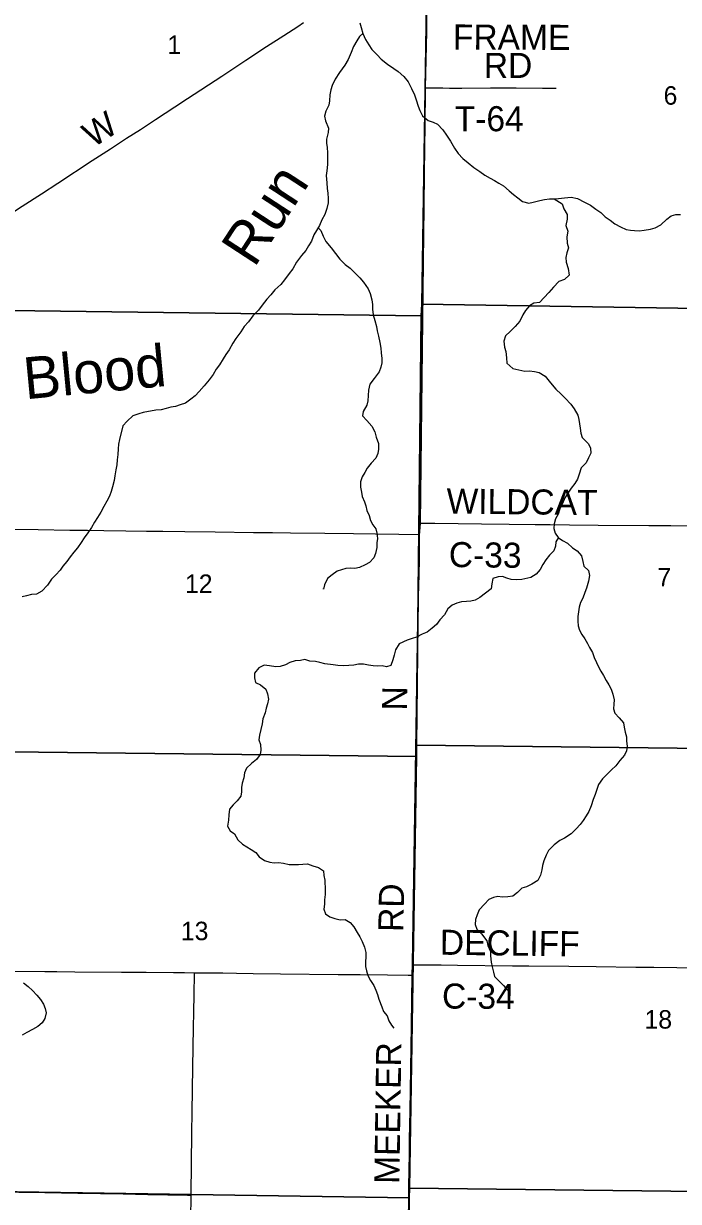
# Model space of a CAD drawing. Extents: x 1584893 to 1934202, y 663575 to 1091909.
# Drawn here: x 1740237 to 1748072, y 948034 to 962130 of the extents above; entities that cross this region are included whole.
import ezdxf

# ---------------------------------------------------------------- set-up
doc = ezdxf.new("R2010")
doc.units = 0
for name, color, linetype in [('GM_X_County_Road', 7, 'Continuous'), ('GM_X_County_Road_Text', 7, 'Continuous'), ('GM_X_Minor_River', 7, 'Continuous'), ('GM_X_Minor_River_Text', 7, 'Continuous'), ('GM_X_Section', 7, 'Continuous'), ('GM_X_Section_Text', 7, 'Continuous'), ('GM_X_Township', 7, 'Continuous'), ('GM_X_Township_Road', 7, 'Continuous'), ('GM_X_Township_Road_Text', 7, 'Continuous')]:
    doc.layers.add(name, color=color, linetype=linetype)

msp = doc.modelspace()

# ---------------------------------------------------------------- linework, layer by layer
at = {"layer": 'GM_X_County_Road'}
for points in [[(1745047, 961359), (1745060, 962035), (1745060, 962094), (1745063, 962269), (1745065, 962378), (1745071, 962804), (1745072, 962833), (1745078, 963198), (1745078, 963259)], [(1744979, 956151), (1744979, 956193), (1744982, 956456), (1744985, 956653), (1744988, 956866), (1744990, 957030), (1744996, 957243), (1744999, 957637), (1745000, 957785), (1745002, 957916), (1745002, 958014), (1745008, 958293), (1745013, 958621), (1745015, 958867), (1745022, 959278), (1745030, 959934), (1745034, 960361), (1745038, 960639), (1745040, 960918), (1745046, 961329), (1745047, 961359)], [(1744976, 956013), (1744977, 956073), (1744979, 956151)], [(1744979, 956151), (1745004, 956151), (1745159, 956149), (1745717, 956141), (1746045, 956139), (1746357, 956136), (1746537, 956134), (1746767, 956132), (1747111, 956128), (1747718, 956124), (1747980, 956121), (1748620, 956114), (1749014, 956110), (1749342, 956108), (1749899, 956101), (1750293, 956098), (1750752, 956093), (1751097, 956091), (1751474, 956089), (1751818, 956090), (1752179, 956091), (1752183, 956091)], [(1739718, 956080), (1739755, 956080), (1740411, 956074), (1740789, 956068), (1741002, 956065), (1741199, 956062), (1741461, 956059), (1741707, 956057), (1741904, 956056), (1742167, 956052), (1742528, 956047), (1742987, 956040), (1743217, 956039), (1743430, 956036), (1743841, 956032), (1744185, 956027), (1744448, 956023), (1744727, 956018), (1744957, 956014), (1744976, 956013)], [(1744892, 950867), (1744895, 951074), (1744900, 951378), (1744905, 951681), (1744909, 951993), (1744920, 952633), (1744925, 953027), (1744930, 953289), (1744934, 953486), (1744939, 953864), (1744941, 954060), (1744944, 954307), (1744947, 954421), (1744954, 954749), (1744957, 954897), (1744960, 955028), (1744962, 955143), (1744963, 955274), (1744969, 955537), (1744973, 955717), (1744975, 955963), (1744976, 956013)], [(1739680, 950791), (1739882, 950789), (1740129, 950788), (1740490, 950787), (1740637, 950785), (1740850, 950783), (1741408, 950779), (1741704, 950777), (1742032, 950773), (1742163, 950772), (1742283, 950771)], [(1744890, 950741), (1744891, 950812), (1744892, 950867)], [(1744892, 950867), (1744922, 950867), (1745070, 950867), (1745233, 950864), (1745430, 950861), (1746086, 950854), (1746283, 950852), (1746759, 950848), (1747087, 950844), (1747562, 950839), (1747776, 950838), (1748054, 950834), (1748399, 950829)], [(1742242, 948109), (1742242, 948116), (1742252, 948854), (1742256, 949100), (1742263, 949641), (1742272, 950117), (1742275, 950297), (1742277, 950511), (1742282, 950756), (1742283, 950771)], [(1742283, 950771), (1742442, 950769), (1742622, 950768), (1742786, 950766), (1742983, 950763), (1743312, 950759), (1744001, 950751), (1744263, 950749), (1744591, 950745), (1744837, 950742), (1744890, 950741)], [(1744824, 945592), (1744824, 945594), (1744825, 945791), (1744828, 946070), (1744832, 946513), (1744835, 946776), (1744835, 946989), (1744838, 947301), (1744841, 947695), (1744846, 948187), (1744850, 948433), (1744854, 948581), (1744856, 948777), (1744859, 948941), (1744861, 949122), (1744870, 949614), (1744874, 949893), (1744877, 950123), (1744884, 950435), (1744889, 950681), (1744890, 950741)], [(1739630, 948155), (1739854, 948154), (1740181, 948146), (1740329, 948144), (1740493, 948141), (1740887, 948133), (1741428, 948123), (1741723, 948118), (1742198, 948109), (1742242, 948109)], [(1742175, 944169), (1742176, 944279), (1742187, 944853), (1742189, 945050), (1742192, 945230), (1742198, 945525), (1742204, 945902), (1742216, 946542), (1742221, 946837), (1742227, 947181), (1742238, 947821), (1742242, 948109)]]:
    msp.add_lwpolyline(points, dxfattribs=at)
at = {"layer": 'GM_X_Minor_River'}
for points in [[(1744259, 962137), (1744275, 962084), (1744298, 962012), (1744327, 961939), (1744367, 961877), (1744404, 961820), (1744466, 961757), (1744517, 961702), (1744593, 961643), (1744667, 961592), (1744718, 961556), (1744786, 961495), (1744837, 961432), (1744879, 961351), (1744916, 961275), (1744934, 961218), (1744959, 961142), (1744978, 961089), (1745010, 961025), (1745077, 960970), (1745137, 960949), (1745191, 960925), (1745255, 960858), (1745298, 960793), (1745344, 960722), (1745393, 960640), (1745436, 960573), (1745494, 960516), (1745556, 960463), (1745623, 960406), (1745697, 960358), (1745757, 960317), (1745819, 960280), (1745870, 960253), (1745924, 960221), (1745978, 960186), (1746046, 960129), (1746097, 960086), (1746151, 960044), (1746207, 960001), (1746281, 959982), (1746335, 959994), (1746414, 960013), (1746468, 960025), (1746528, 960032), (1746584, 960033)], [(1744298, 962011), (1744255, 961976), (1744225, 961922), (1744186, 961856), (1744157, 961782), (1744120, 961700), (1744079, 961630), (1744018, 961543), (1743965, 961465), (1743928, 961389), (1743912, 961335), (1743903, 961275), (1743898, 961205), (1743890, 961153), (1743853, 961081), (1743836, 961023), (1743850, 960964), (1743885, 960878), (1743882, 960825), (1743863, 960747), (1743863, 960697), (1743868, 960647), (1743874, 960581), (1743875, 960502), (1743874, 960444), (1743865, 960368), (1743859, 960310), (1743866, 960223), (1743871, 960157), (1743877, 960101), (1743880, 960036), (1743880, 959986), (1743867, 959916), (1743840, 959844), (1743807, 959782), (1743776, 959712), (1743740, 959652), (1743711, 959600), (1743684, 959526), (1743648, 959471), (1743613, 959415), (1743562, 959355), (1743503, 959273), (1743458, 959193), (1743413, 959140), (1743358, 959062), (1743316, 959006), (1743245, 958943), (1743196, 958883), (1743149, 958831), (1743090, 958761), (1743048, 958700), (1742981, 958630), (1742930, 958562), (1742877, 958503), (1742836, 958439), (1742775, 958359), (1742741, 958303), (1742698, 958227), (1742659, 958169), (1742624, 958116), (1742583, 958046), (1742543, 957994), (1742504, 957928), (1742457, 957868), (1742398, 957793), (1742337, 957727), (1742291, 957673), (1742240, 957634), (1742173, 957588), (1742109, 957567), (1742055, 957547), (1741998, 957538), (1741944, 957524), (1741884, 957509), (1741820, 957505), (1741669, 957477), (1741616, 957461), (1741544, 957434), (1741475, 957370), (1741426, 957316), (1741384, 957153)], [(1746584, 960033), (1746682, 959974), (1746701, 959912), (1746739, 959845), (1746740, 959787), (1746723, 959715), (1746749, 959646), (1746736, 959576), (1746741, 959502), (1746755, 959447), (1746738, 959385), (1746723, 959329), (1746727, 959273), (1746752, 959199), (1746763, 959120), (1746709, 959066), (1746642, 959043), (1746579, 958977), (1746520, 958910), (1746466, 958850), (1746411, 958792), (1746343, 958783), (1746290, 958751), (1746243, 958694), (1746211, 958642), (1746176, 958570), (1746117, 958504), (1746058, 958445), (1746002, 958391), (1745985, 958327), (1745990, 958257), (1746008, 958204), (1746017, 958130), (1746018, 958064), (1746090, 958001), (1746164, 957984), (1746236, 957971), (1746290, 957973), (1746350, 957966), (1746404, 957955), (1746476, 957908), (1746541, 957831), (1746605, 957755), (1746668, 957696), (1746718, 957645), (1746783, 957574), (1746823, 957521), (1746868, 957445), (1746882, 957390), (1746889, 957340), (1746897, 957286), (1746906, 957227), (1746922, 957175)], [(1746584, 960033), (1746638, 960035), (1746707, 960046), (1746787, 960051), (1746863, 960035), (1746949, 959994), (1747021, 959955), (1747085, 959908), (1747144, 959867), (1747196, 959818), (1747254, 959776), (1747313, 959733), (1747377, 959698), (1747445, 959667), (1747497, 959659), (1747547, 959652), (1747601, 959650), (1747664, 959657), (1747738, 959670), (1747792, 959686), (1747863, 959721), (1747934, 959787), (1747986, 959828), (1748041, 959846), (1748095, 959845)], [(1743760, 959685), (1743794, 959654), (1743821, 959587), (1743855, 959521), (1743918, 959444), (1744021, 959312), (1744083, 959247), (1744144, 959201), (1744200, 959146), (1744259, 959087), (1744305, 959036), (1744360, 958956), (1744382, 958901), (1744403, 958825), (1744411, 958768), (1744412, 958710), (1744421, 958642), (1744439, 958577), (1744460, 958505), (1744469, 958451), (1744483, 958388), (1744498, 958314), (1744511, 958245), (1744517, 958189), (1744524, 958123), (1744522, 958069), (1744511, 958018), (1744492, 957960), (1744431, 957883), (1744381, 957813), (1744364, 957743), (1744359, 957677), (1744356, 957614), (1744346, 957564), (1744301, 957487), (1744292, 957434), (1744346, 957378), (1744405, 957311), (1744441, 957244), (1744456, 957180)], [(1741384, 957153), (1741375, 957095), (1741370, 957041), (1741365, 956971), (1741357, 956907), (1741353, 956849), (1741342, 956789), (1741328, 956719), (1741321, 956663), (1741302, 956587), (1741285, 956531), (1741264, 956473), (1741235, 956416), (1741196, 956352), (1741161, 956283), (1741122, 956219), (1741087, 956161), (1741050, 956100), (1741007, 956036), (1740964, 955977), (1740925, 955918), (1740882, 955856), (1740839, 955803), (1740794, 955749), (1740755, 955692), (1740706, 955638), (1740677, 955587), (1740624, 955534), (1740573, 955480), (1740522, 955409), (1740456, 955336), (1740392, 955303), (1740334, 955296), (1740271, 955281), (1740221, 955270)], [(1744456, 957180), (1744483, 957103), (1744482, 957038), (1744475, 956986), (1744452, 956929), (1744397, 956867), (1744350, 956810), (1744321, 956758), (1744290, 956705), (1744267, 956647), (1744268, 956581), (1744279, 956521), (1744290, 956470), (1744317, 956408), (1744334, 956357), (1744345, 956301), (1744374, 956242), (1744387, 956184), (1744417, 956131), (1744450, 956081), (1744465, 956030), (1744470, 955966), (1744463, 955914), (1744464, 955858), (1744449, 955788), (1744426, 955736), (1744375, 955679), (1744323, 955652), (1744258, 955621), (1744202, 955610), (1744146, 955611), (1744094, 955608), (1744043, 955594), (1743989, 955577), (1743930, 955534), (1743875, 955487), (1743836, 955413), (1743825, 955361), (1743825, 955367)], [(1746922, 957175), (1746998, 957100), (1747019, 957049), (1747024, 956987), (1746997, 956931), (1746970, 956872), (1746909, 956812), (1746886, 956739), (1746865, 956677), (1746832, 956625), (1746789, 956568), (1746750, 956508), (1746711, 956453), (1746686, 956385), (1746655, 956321), (1746634, 956260), (1746601, 956202), (1746584, 956142), (1746583, 956086), (1746596, 956032), (1746633, 955981), (1746684, 955944), (1746744, 955913), (1746805, 955854), (1746861, 955821), (1746914, 955760), (1746929, 955692), (1746940, 955635), (1746997, 955584), (1747010, 955524), (1746997, 955456), (1746973, 955374), (1746952, 955320), (1746927, 955255), (1746902, 955201), (1746883, 955147), (1746877, 955089), (1746870, 955033), (1746869, 954979), (1746874, 954921), (1746887, 954870), (1746918, 954820), (1746951, 954765), (1746984, 954712), (1747008, 954662), (1747043, 954603), (1747062, 954543), (1747091, 954482), (1747116, 954432), (1747143, 954381), (1747176, 954328), (1747207, 954268), (1747239, 954215), (1747268, 954165), (1747287, 954104), (1747304, 954036), (1747299, 953986), (1747294, 953930), (1747311, 953875), (1747362, 953822), (1747413, 953763), (1747422, 953709), (1747433, 953651), (1747451, 953594), (1747452, 953542), (1747457, 953482), (1747450, 953428), (1747425, 953376), (1747372, 953311), (1747323, 953246), (1747270, 953200), (1747164, 953090), (1747117, 953024), (1747096, 952965), (1747077, 952905), (1747052, 952845), (1747028, 952769), (1747001, 952702), (1746970, 952650), (1746933, 952594), (1746897, 952543), (1746850, 952492), (1746787, 952434), (1746708, 952382), (1746653, 952352), (1746586, 952303), (1746519, 952232), (1746490, 952177), (1746461, 952111), (1746446, 952055), (1746437, 952001), (1746422, 951939), (1746391, 951876), (1746318, 951829), (1746256, 951800), (1746199, 951781), (1746148, 951729), (1746092, 951688), (1746031, 951679), (1745965, 951674), (1745911, 951681)], [(1746636, 955978), (1746604, 955927), (1746603, 955875), (1746582, 955819), (1746529, 955766), (1746484, 955711), (1746451, 955657), (1746418, 955596), (1746371, 955542), (1746305, 955499), (1746200, 955477), (1746130, 955472), (1746072, 955477), (1746020, 955494), (1745968, 955513), (1745916, 955508), (1745850, 955489), (1745841, 955423), (1745832, 955363), (1745765, 955314), (1745696, 955263), (1745641, 955228), (1745589, 955218), (1745535, 955215), (1745477, 955210), (1745422, 955193), (1745364, 955170), (1745313, 955125), (1745272, 955053), (1745217, 954994), (1745178, 954938), (1745125, 954893), (1745066, 954846), (1745008, 954821), (1744939, 954788), (1744885, 954769), (1744826, 954750), (1744730, 954707), (1744686, 954634), (1744673, 954572), (1744656, 954514), (1744633, 954448), (1744581, 954431), (1744527, 954444), (1744475, 954439), (1744419, 954444), (1744363, 954453), (1744303, 954464), (1744243, 954463), (1744187, 954453), (1744127, 954446), (1744066, 954443), (1743998, 954448), (1743940, 954455), (1743840, 954467), (1743781, 954482), (1743729, 954497), (1743663, 954498), (1743603, 954519), (1743551, 954508), (1743485, 954505), (1743424, 954482), (1743372, 954457), (1743309, 954436), (1743255, 954432), (1743179, 954442), (1743115, 954451), (1743053, 954418), (1743002, 954356), (1742999, 954298), (1743014, 954244), (1743071, 954215), (1743135, 954166), (1743156, 954107), (1743169, 954043), (1743154, 953987), (1743139, 953935), (1743128, 953881), (1743099, 953810), (1743092, 953748), (1743075, 953680), (1743059, 953614), (1743053, 953558), (1743072, 953503), (1743075, 953435), (1743066, 953381), (1743025, 953322), (1742964, 953273), (1742905, 953217), (1742880, 953162), (1742873, 953102), (1742852, 953038), (1742845, 952986), (1742844, 952936), (1742837, 952884), (1742794, 952826), (1742743, 952781), (1742702, 952730), (1742693, 952660), (1742688, 952595), (1742679, 952523)], [(1742679, 952523), (1742708, 952469), (1742760, 952432), (1742802, 952361), (1742856, 952308), (1742907, 952279), (1742959, 952244), (1743016, 952209), (1743057, 952159), (1743119, 952115), (1743183, 952092), (1743236, 952085), (1743289, 952089), (1743349, 952080), (1743414, 952067), (1743474, 952066), (1743527, 952067), (1743577, 952068), (1743633, 952073), (1743700, 952048), (1743764, 952029), (1743824, 951990), (1743831, 951933), (1743840, 951877), (1743844, 951757), (1743847, 951705), (1743836, 951645), (1743839, 951591), (1743828, 951531), (1743849, 951474), (1743901, 951439), (1743962, 951418), (1744026, 951405), (1744084, 951406), (1744146, 951371), (1744187, 951318), (1744228, 951251), (1744259, 951199), (1744288, 951146), (1744317, 951078), (1744332, 951011), (1744333, 950959), (1744328, 950903), (1744327, 950845), (1744339, 950795), (1744356, 950738), (1744389, 950678), (1744426, 950617), (1744451, 950560), (1744470, 950510), (1744489, 950453), (1744524, 950363), (1744545, 950306), (1744586, 950253), (1744607, 950195), (1744638, 950144), (1744666, 950106)], [(1745911, 951681), (1745859, 951672), (1745803, 951649), (1745752, 951593), (1745690, 951522), (1745665, 951465), (1745644, 951409), (1745641, 951347), (1745662, 951292), (1745714, 951237), (1745778, 951154), (1745793, 951096), (1745822, 951023), (1745823, 950973), (1745832, 950899), (1745845, 950840), (1745858, 950776), (1745873, 950724), (1745927, 950671), (1745978, 950616), (1746027, 950563), (1746029, 950559)], [(1740237, 950649), (1740292, 950606), (1740346, 950557), (1740397, 950504), (1740438, 950449), (1740475, 950394), (1740496, 950342), (1740509, 950290), (1740490, 950224), (1740459, 950172), (1740407, 950127), (1740346, 950090), (1740277, 950057), (1740221, 950024)]]:
    msp.add_lwpolyline(points, dxfattribs=at)
at = {"layer": 'GM_X_Section'}
for points in [[(1739799, 963975), (1745081, 963910), (1745001, 958773), (1744996, 958632), (1739748, 958699)], [(1745081, 963910), (1750963, 963989), (1750873, 958681), (1745001, 958773)], [(1739748, 958699), (1744996, 958632), (1744940, 953492), (1744937, 953360), (1739713, 953417)], [(1745001, 958773), (1750873, 958681), (1750828, 953428), (1744940, 953492), (1744996, 958632)], [(1744940, 953492), (1750828, 953428), (1750761, 948123), (1744853, 948192), (1744937, 953360)], [(1739713, 953417), (1744937, 953360), (1744853, 948192), (1744850, 948076), (1739636, 948157)], [(1739636, 948157), (1744850, 948076), (1744794, 942974), (1744791, 942835), (1739520, 942867)], [(1744853, 948192), (1750761, 948123), (1750676, 942925), (1744794, 942974), (1744850, 948076)]]:
    msp.add_lwpolyline(points, close=True, dxfattribs=at)
at = {"layer": 'GM_X_Township'}
for points in [[(1744819, 945591), (1744887, 950744), (1744891, 950875), (1744970, 956008), (1744981, 956147), (1745043, 961357), (1745072, 963255)], [(1745072, 963255), (1745043, 961357), (1744981, 956147), (1744970, 956008), (1744891, 950875), (1744887, 950744), (1744819, 945591)]]:
    msp.add_lwpolyline(points, dxfattribs=at)
at = {"layer": 'GM_X_Township_Road'}
for points in [[(1739766, 959651), (1739873, 959722), (1740012, 959809), (1740219, 959943), (1740453, 960094), (1740646, 960219), (1741058, 960489), (1741278, 960632), (1741470, 960757), (1741637, 960863), (1741814, 960980), (1742047, 961135), (1742198, 961234), (1742611, 961502), (1742898, 961692), (1743145, 961854), (1743351, 961988), (1743517, 962095), (1743585, 962141)], [(1745047, 961359), (1745073, 961359), (1745122, 961360), (1745187, 961361), (1745252, 961359), (1745334, 961357), (1745481, 961357), (1745824, 961359), (1746037, 961360), (1746129, 961359)], [(1746129, 961359), (1746445, 961356), (1746576, 961356), (1746609, 961358)]]:
    msp.add_lwpolyline(points, dxfattribs=at)

# ---------------------------------------------------------------- texts
at = {"layer": 'GM_X_County_Road_Text'}
for s, rotation, p in [('WILDCAT', 359.4063, (1745297, 956266)), ('C-33', 359.3142, (1745324, 955626)), ('N', 89.1148, (1744825, 953907)), ('RD', 89.0128, (1744781, 951257)), ('DECLIFF', 359.3248, (1745217, 950986)), ('C-34', 359.6571, (1745243, 950342)), ('MEEKER', 89.1689, (1744733, 948242))]:
    msp.add_text(s, height=300, rotation=rotation, dxfattribs=at).set_placement(p)
at = {"layer": 'GM_X_Minor_River_Text'}
for s, height, rotation, p in [('Run', 500.2, 56.8985, (1742997, 959198)), ('Blood', 500.1, 5.4377, (1740259, 957632))]:
    msp.add_text(s, height=height, rotation=rotation, dxfattribs=at).set_placement(p)
at = {"layer": 'GM_X_Section_Text'}
for s, p in [('1', (1741958, 961767)), ('6', (1747895, 961159)), ('7', (1747821, 955394)), ('12', (1742169, 955316)), ('13', (1742120, 951160)), ('18', (1747667, 950102))]:
    msp.add_text(s, height=221, rotation=0, dxfattribs=at).set_placement(p)
at = {"layer": 'GM_X_Township_Road_Text'}
for s, rotation, p in [('FRAME', 359.7997, (1745374, 961819)), ('RD', 0, (1745744, 961479)), ('W', 32.691, (1741069, 960638)), ('T-64', 0, (1745396, 960841))]:
    msp.add_text(s, height=300, rotation=rotation, dxfattribs=at).set_placement(p)

doc.saveas('drawing.dxf')
